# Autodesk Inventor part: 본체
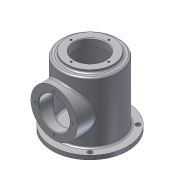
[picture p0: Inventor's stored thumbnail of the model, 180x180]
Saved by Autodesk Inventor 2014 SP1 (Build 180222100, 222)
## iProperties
Created: 2014-10
Part Number: 본체
Material: 알루미늄 6061
Document SubType Name: Modeling
Designer: KYOUNG IL JANG
Density: 2.71 g/cm^3
Appearance: 알루미늄 - 평지
Author: KYOUNG IL JANG
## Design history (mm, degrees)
sketch "스케치1"
  geometry: C1 r 50 at (0, 0); 1 further point
  constraints: 1 centre point, 1 coincident
  dimensions: "d15" = 100 diameter of C1
extrude "돌출1" new body sketch "스케치1" distance "d2" = 112; taper "d3" = 0 deg
sketch "스케치2"
  geometry: L1 (50, 112)-(-50, 112) reference; C1 r 40 at (0, 55); 1 further point
  constraints: 1 centre point, 1 vertical alignment
  dimensions: "d16" = 80 diameter of C1; "d48" = 57 distance from line of C1.centre L1
extrude "돌출2" join sketch "스케치2" distance "d18" = 62; taper "d19" = 0 deg
sketch "스케치3"
  geometry: C1 r 50 at (0, 0) reference; C2 r 65 at (0, 0); 1 further point
  constraints: 1 centre point, 1 coincident
  dimensions: "d20" = 130 diameter of C2
extrude "돌출3" join sketch "스케치3" distance "d21" = 7; taper "d22" = 0 deg
sketch "스케치4"
  geometry: C1 r 45 at (0, 0); 1 further point
  constraints: 1 centre point, 1 coincident
  dimensions: "d23" = 90 diameter of C1
extrude "돌출4" cut sketch "스케치4" distance "d24" = 97; taper "d25" = 0 deg
sketch "스케치5"
  geometry: C1 r 40 at (0, 0); 1 further point
  constraints: 1 centre point, 1 coincident
  dimensions: "d26" = 80 diameter of C1
extrude "돌출5" join sketch "스케치5" distance "d27" = 5; taper "d28" = 0 deg
hole "구멍2" diameter "d31" = 54; stored, may be unused: countersink angle "d35" = 90 deg, drill point angle "d37" = 118 deg; dims "d29" = 10, "d30" = 10, "d32" = 6, "d33" = 4, "d34" = 2, "d36" = 8
hole "구멍3" diameter "d40" = 54; stored, may be unused: countersink angle "d44" = 90 deg, drill point angle "d46" = 118 deg; dims "d38" = 10, "d39" = 10, "d41" = 6, "d42" = 4, "d43" = 2, "d45" = 8
fillet "모깎기1" dims "d47" = 3
chamfer "모따기1" distance "d49" = 1; stored, may be unused: second distance "d50" = 2, angle "d51" = 45 deg
sketch "스케치6"
  geometry: L1 (0, 0)-(58.5, 0); A1 r 58.5 centre (0, 0) between (41.366, 41.366) and (58.5, 0); 1 further point
  constraints: 2 end point, 2 point on circle, 1 centre point, 1 coincident, 1 horizontal
  dimensions: "d52" = 117 diameter of A1; "d85" = 45 deg dimension on point (0, 0) A1.start L1.end
hole "구멍4" sketch "스케치6" at (41.366, 41.366) diameter "d53" = 8; stored, may be unused: countersink angle "d57" = 90 deg, drill point angle "d59" = 118 deg; dims "d54" = 6, "d55" = 4, "d56" = 2, "d58" = 8
sketch "스케치7" dims "d63" = 65
  geometry: C1 r 40 at (0, 0) reference; 3 further points
  constraints: 2 horizontal alignment, 1 coincident, 2 other
hole "구멍5" sketch "스케치7" at (32.5, 0) diameter "d64" = 3.242; stored, may be unused: countersink angle "d68" = 90 deg, drill point angle "d70" = 118 deg; dims "d65" = 8, "d66" = 8, "d67" = 4.4, "d69" = 10
sketch "스케치8" dims "d74" = 65
  geometry: 3 further points
  constraints: 2 horizontal alignment, 1 coincident, 2 other
hole "구멍6" sketch "스케치8" at (32.5, 0) diameter "d75" = 3.242; stored, may be unused: countersink angle "d79" = 90 deg, drill point angle "d81" = 118 deg; dims "d76" = 8, "d77" = 8, "d78" = 4.4, "d80" = 10
node "작업 평면1"
node "작업 평면2"
sketch "스케치9"
  geometry: L1 (-5, 33)-(5, 33); L2 (5, 33)-(5, 77); L3 (5, 77)-(-5, 77); L4 (-5, 77)-(-5, 33); L5 (-5, 33)-(5, 77); L6 (5, 33)-(-5, 77); 4 further points
  constraints: 12 end point, 3 midpoint, 2 parallel, 1 coincident, 1 horizontal, 1 perpendicular, 1 vertical alignment
  dimensions: "d86" = 10 distance of L3.end L2.end; "d87" = 44 distance of L2.end L1.end; "d88" = 55 distance of point (0, 0) point (0, 55)
extrude "돌출6" join sketch "스케치9" stored distance "d90" = 6; taper "d91" = 0 deg
sketch "스케치10"
  geometry: L1 (33, 5)-(77, 5) reference; L2 (33, -5)-(33, 5) reference; 4 further points
  constraints: 2 midpoint, 1 horizontal alignment, 1 vertical alignment, 1 other
feature "엠보싱1" sketch "스케치10" dims "d15" = 100, "d92" = 0.5, "d93" = 0
node "솔리드1"
pattern_circular "원형 패턴1" dims angle "d61" = 360 deg
pattern_circular "원형 패턴2" dims angle "d72" = 360 deg
pattern_circular "원형 패턴3" dims angle "d83" = 360 deg
node "투영된 루프1"
node "참조1"
other parameters: "d89" = -1
